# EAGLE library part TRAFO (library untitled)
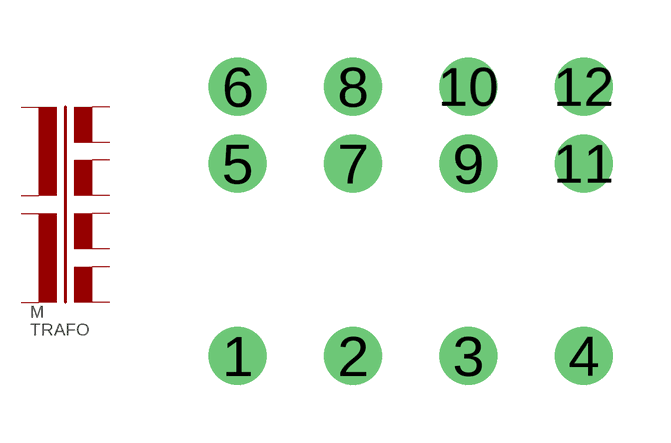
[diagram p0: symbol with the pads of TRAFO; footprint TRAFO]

Designator prefix M

## TRAFO  [TRAFO]
1  1  pas
2  2  pas
3  3  pas
4  4  pas
5  5  pas
6  6  pas
7  7  pas
8  8  pas
9  9  pas
10  10  pas
11  11  pas
12  12  pas

## Footprint TRAFO (pad centres in mm)
drill 1 round: 1 -4,-3; 2 -1,-3; 3 2,-3; 4 5,-3; 5 -4,2; 6 -4,4; 7 -1,2; 8 -1,4; 9 2,2; 10 2,4; 11 5,2; 12 5,4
